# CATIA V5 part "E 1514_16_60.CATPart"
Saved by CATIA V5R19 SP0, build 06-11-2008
Definition: E 1514_16_60
Nomenclature: E 1514_16_60
Description: PART-E 1514_16_60_2-DESC
Material "Steel": density 7860 kg/m3, Young's modulus 2e+11 Pa, Poisson ratio 0.266, thermal expansion 1.17e-05 1/K
Bounding box of the stored display mesh (mm): x -11 to 11, y -14 to 14, z 0 to 60
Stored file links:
  G:\UTB\Kombinované\Bakalářská práce\Catia\FORMA\E 1514_16_60.CATPart
  D:\Aplikace\CATIA\Nová složka\win_b64\startup\materials\Catalog.CATMaterial
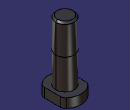
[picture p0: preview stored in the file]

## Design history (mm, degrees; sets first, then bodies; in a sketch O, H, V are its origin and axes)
Body1 "E 1514_16_60" (main body)
  Solid1: solid without history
